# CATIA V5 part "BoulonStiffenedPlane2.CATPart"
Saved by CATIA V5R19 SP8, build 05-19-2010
Part number: BoulonStiffenedPlane2
Bounding box of the stored display mesh (mm): x -28 to 24, y 892 to 908, z 392 to 408
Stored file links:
  G:\EU_thinkMotion\CFAO_2010\MMS_groupe3\MMS_groupe3\A reprendre\fovide\fovide\BoulonStiffenedPlane2.CATPart
  C:\Users\Rodger\Desktop\Part11.CATPart
  G:\EU_thinkMotion\CFAO_2010\MMS_groupe3\MMS_groupe3\A reprendre\fovide\fovide\fovide.CATProduct
  G:\EU_thinkMotion\CFAO_2010\MMS_groupe3\MMS_groupe3\A reprendre\fovide\fovide\Stiffened Plane 28.CATPart
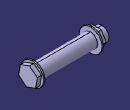
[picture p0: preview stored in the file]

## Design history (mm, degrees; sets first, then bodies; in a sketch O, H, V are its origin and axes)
Parameters
  Diametre = 10 mm
  Longueur = 40 mm
Set1
  DatumSurface1: linked copy from another document
  Point1: linked copy from another document
Body1 (main body)
Body2
  Sketch1 on DatumSurface1, origin (20, 0, 20), H (0, 0, -1), V (0, 1, 0)
    circle A1 centre (-380, 900) radius 8
    point P1 (-380, 900)
    reference projected point E1 (-380, 900) from Point1
    radius A1 = 8 {= Diametre *8/10}
    coincidence: P1 E1
  Pad1: profile Sketch1, direction (1, 0, 0), length 1
  Sketch2 on end face of Pad1, origin (21, 0, 22), H (0, 0, -1), V (0, 1, 0)
    point P1 (-378, 900)
    point P2 (-375.5061, 893.4593)
    point P3 (-371.0887, 898.8894)
    point P4 (-373.5825, 905.4301)
    point P5 (-380.4939, 906.5407)
    point P6 (-384.9113, 901.1106)
    point P7 (-382.4175, 894.5699)
    point P8 (-373.2974, 896.1744)
    line L1 (-375.5061, 893.4593) -> (-371.0887, 898.8894)
    line L2 (-371.0887, 898.8894) -> (-373.5825, 905.4301)
    line L3 (-373.5825, 905.4301) -> (-380.4939, 906.5407)
    line L4 (-380.4939, 906.5407) -> (-384.9113, 901.1106)
    line L5 (-384.9113, 901.1106) -> (-382.4175, 894.5699)
    line L6 (-382.4175, 894.5699) -> (-375.5061, 893.4593)
    construction line L7 (-378, 900) -> (-373.2974, 896.1744)
    construction circle A1 centre (-378, 900) radius 7
    construction arc A2 centre (-384.9113, 901.1106) radius 7 from (-380.4939, 906.5407) to (-382.4175, 894.5699) cw
    construction arc A3 centre (-371.0887, 898.8894) radius 7 from (-373.5825, 905.4301) to (-375.5061, 893.4593) ccw
    reference projected point E1 (-378, 900) from Point1
    radius A1 = 7 {= Diametre *7/10}
    coincidence: A1 P2, A1 P3, A1 P4, A1 P5, A1 P6, A1 P7, A2 P1, A3 P1, P1 E1
    midpoint: P8 L1
    parallelism: L1 L4
  Pad2: profile Sketch2, direction (1, 0, 0), length 3
  Sketch3 on start face of Pad1, origin (20, 0, 20), H (0, 0, -1), V (0, -1, 0)
    circle A1 centre (-380, -900) radius 5
    point P1 (-380, -900)
    reference projected point E1 (-380, -900) from Point1
    radius A1 = 5 {= Diametre /2}
    coincidence: P1 E1
  Pad3: profile Sketch3, direction (-1, 0, 0), length 40 {= Longueur}
  Sketch4 on end face of Pad3, origin (-20, 0, -60), H (0, 0, -1), V (0, -1, 0)
    circle A1 centre (-460, -900) radius 8
    point P1 (-460, -900)
    reference projected point E1 (-460, -900) from Point1
    radius A1 = 8 {= Diametre *8/10}
    coincidence: P1 E1
  Pad4: profile Sketch4, direction (-1, 0, 0), length 1
  Sketch5 on end face of Pad4, origin (-21, 0, -62), H (0, 0, -1), V (0, -1, 0)
    point P1 (-462, -900)
    point P2 (-462.0478, -906.9998)
    point P3 (-455.9619, -903.5413)
    point P4 (-455.9141, -896.5415)
    point P5 (-461.9522, -893.0002)
    point P6 (-468.0381, -896.4587)
    point P7 (-468.0859, -903.4585)
    point P8 (-459.0048, -905.2706)
    line L1 (-462.0478, -906.9998) -> (-455.9619, -903.5413)
    line L2 (-455.9619, -903.5413) -> (-455.9141, -896.5415)
    line L3 (-455.9141, -896.5415) -> (-461.9522, -893.0002)
    line L4 (-461.9522, -893.0002) -> (-468.0381, -896.4587)
    line L5 (-468.0381, -896.4587) -> (-468.0859, -903.4585)
    line L6 (-468.0859, -903.4585) -> (-462.0478, -906.9998)
    construction line L7 (-462, -900) -> (-459.0048, -905.2706)
    construction circle A1 centre (-462, -900) radius 7
    construction arc A2 centre (-468.0381, -896.4587) radius 7 from (-461.9522, -893.0002) to (-468.0859, -903.4585) cw
    construction arc A3 centre (-455.9619, -903.5413) radius 7 from (-455.9141, -896.5415) to (-462.0478, -906.9998) ccw
    reference projected point E1 (-462, -900) from Point1
    radius A1 = 7 {= Diametre *7/10}
    coincidence: A1 P2, A1 P3, A1 P4, A1 P5, A1 P6, A1 P7, A2 P1, A3 P1, P1 E1
    midpoint: P8 L1
    parallelism: L1 L4
  Pad5: profile Sketch5, direction (-1, 0, 0), length 3
  Sketch6 on end face of Pad5, origin (-24, 0, -68), H (0, 0, -1), V (0, -1, 0)
    circle A1 centre (-468, -900) radius 5
    point P1 (-468, -900)
    reference projected point E1 (-468, -900) from Point1
    radius A1 = 5 {= Diametre /2}
    coincidence: P1 E1
  Pad6: profile Sketch6, direction (-1, 0, 0), length 4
